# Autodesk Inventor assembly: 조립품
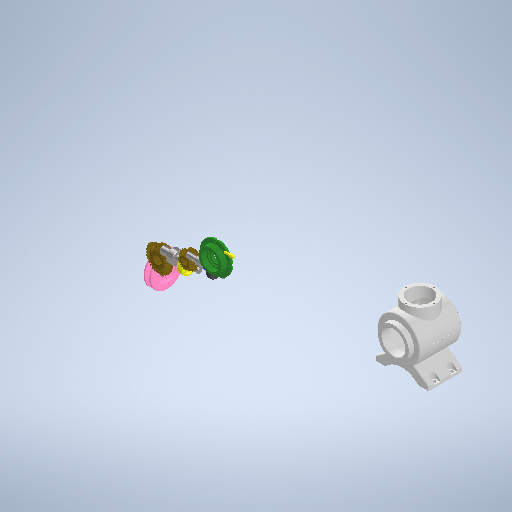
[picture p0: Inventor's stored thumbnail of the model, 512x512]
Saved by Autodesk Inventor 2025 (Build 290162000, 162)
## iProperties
Created: 2024-07
Part Number: 조립품
Document SubType Name: Assembly
Designer: hsj03
Author: hsj03
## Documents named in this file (15)
- C:\Users\hsj03\OneDrive\바탕 화면\740709V1007\조립품.iam
- C:\Users\hsj03\OneDrive\바탕 화면\740709V1007\본체.ipt
- C:\Users\hsj03\OneDrive\바탕 화면\인벤터\20240615\공용부품_20240615_2\V-벨트풀리\V-벨트풀리.ipt
- C:\Users\hsj03\OneDrive\바탕 화면\인벤터\20240615\공용부품_20240615_2\메인 베벨기어\메인 베벨기어.ipt
- C:\Users\hsj03\OneDrive\바탕 화면\인벤터\20240615\공용부품_20240615_2\메인 축\메인 축.ipt
- C:\Users\hsj03\OneDrive\바탕 화면\인벤터\20240615\공용부품_20240615_2\베어링 6203\베어링 6203.ipt
- C:\Users\hsj03\OneDrive\바탕 화면\인벤터\20240615\공용부품_20240615_2\볼트 M4 x 10\볼트 M4 x 10.ipt
- C:\Users\hsj03\OneDrive\바탕 화면\인벤터\20240615\공용부품_20240615_2\서브 베벨기어\서브 베벨기어.ipt
- C:\Users\hsj03\OneDrive\바탕 화면\인벤터\20240615\공용부품_20240615_2\서브 축\서브 축.ipt
- C:\Users\hsj03\OneDrive\바탕 화면\인벤터\20240615\공용부품_20240615_2\오일실 17 x 32 x 8\오일실 17 x 32 x 8.ipt
- C:\Users\hsj03\OneDrive\바탕 화면\인벤터\20240615\공용부품_20240615_2\와셔 4 x 16\와셔 4 x 16.ipt
- C:\Users\hsj03\OneDrive\바탕 화면\인벤터\20240615\공용부품_20240615_2\육각볼트 M4 x 8\육각볼트 M4 x 8.ipt
- C:\Users\hsj03\OneDrive\바탕 화면\인벤터\20240615\공용부품_20240615_2\커버\커버.ipt
- C:\Users\hsj03\OneDrive\바탕 화면\인벤터\20240615\공용부품_20240615_2\키 4 x 4 x 14\키 4 x 4 x 14.ipt
- C:\Users\hsj03\OneDrive\바탕 화면\인벤터\20240615\공용부품_20240615_2\키 5 x 5 x 14\키 5 x 5 x 14.ipt
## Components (2 placed, 1 different names)
1. V-벨트풀리:1
2. V-벨트풀리:2
